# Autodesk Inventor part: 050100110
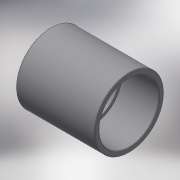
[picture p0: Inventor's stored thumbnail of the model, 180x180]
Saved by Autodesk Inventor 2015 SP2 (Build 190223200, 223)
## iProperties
Created: 2017-10
Part Number: 050100110
Material: Generic
Description: PLASSON SOCKET PVC 110 - CEMENT
Document SubType Name: Modeling
Designer: KIM
Density: 1 g/cm^3
Appearance: Default
Author: KIM
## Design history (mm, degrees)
derived "050100.ipt"
feature "Solid1::050100.ipt"
tag "TaggingFeature1"
body "Solid1"
other parameters: "d0" = 128, "d1" = 126, "d2" = 61, "d3" = 6, "d5" = 99, "d7" = 1.1, "E_" = 126, "H_" = 128, "l_" = 61, "Z_" = 6
